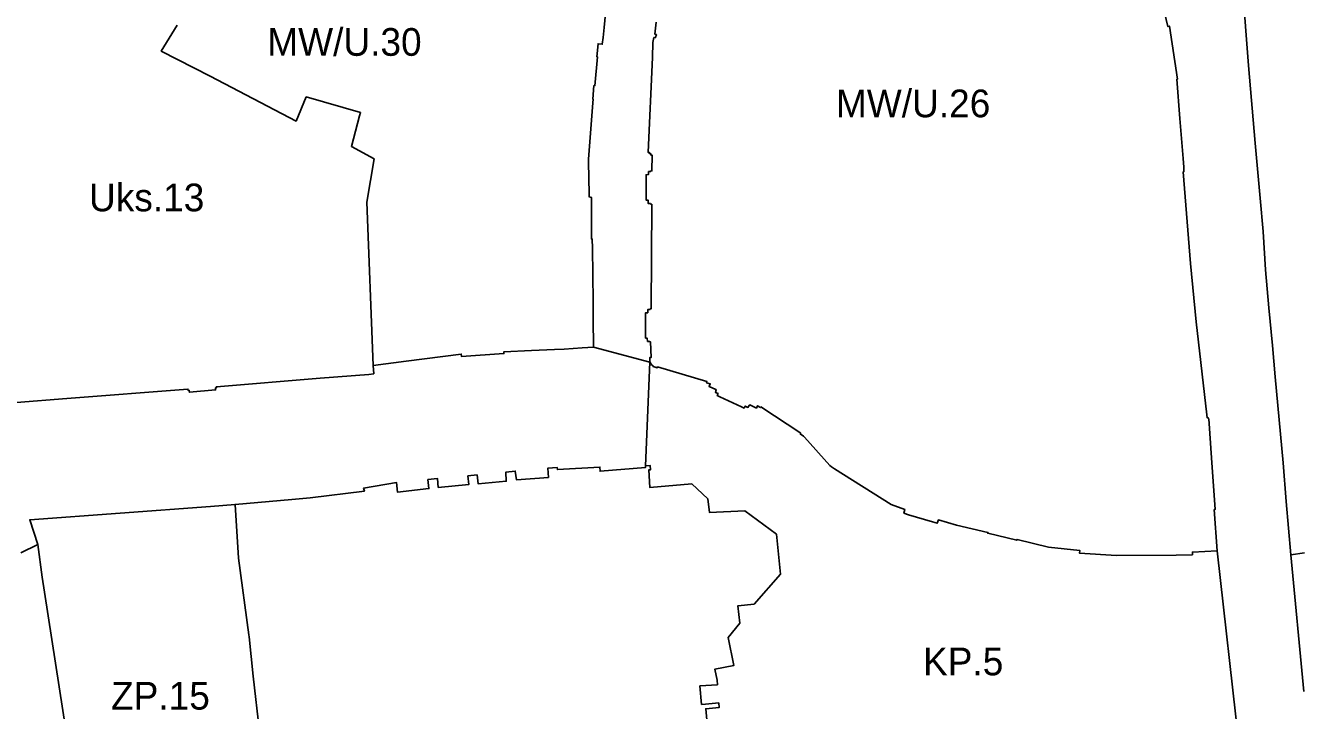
# Model space of a CAD drawing. Extents: x 7423367 to 7424726, y 5546744 to 5548391.
# Drawn here: x 7423725.3 to 7423955.4, y 5547521.4 to 5547645 of the extents above; entities that cross this region are included whole.
import ezdxf

# ---------------------------------------------------------------- set-up
doc = ezdxf.new("R2010")
doc.units = 0
doc.layers.add('linie_rozgraniczajace', color=7, linetype='Continuous')
doc.layers.add('oznaczenia_przeznaczen', color=7, linetype='Continuous')

msp = doc.modelspace()

# ---------------------------------------------------------------- linework, layer by layer
at = {"layer": 'linie_rozgraniczajace'}
for points in [[(7423956.13, 5547549.82), (7423953.67, 5547549.49), (7423952.85, 5547559.12), (7423952.31, 5547566.09), (7423950.87, 5547581.59), (7423950.35, 5547587.25), (7423949.72, 5547594), (7423949.1, 5547600.91), (7423948.68, 5547607.79), (7423948.13, 5547613.84), (7423947.24, 5547623.76), (7423946.05, 5547637.74), (7423944.94, 5547651.91), (7423948.5, 5547670.54), (7423948.98, 5547673.5), (7423949.6, 5547676.37), (7423953.17, 5547690.5), (7423957.42, 5547701.56)], [(7423830.38, 5547651.64), (7423829.69, 5547644.61), (7423829.51, 5547642.82), (7423829.36, 5547641.56), (7423828.61, 5547641.67), (7423828.4, 5547639.3), (7423828.52, 5547639.3), (7423828.06, 5547634.08), (7423827.87, 5547634.11), (7423827.68, 5547631.68), (7423827.73, 5547631.65), (7423827.69, 5547631), (7423826.91, 5547620.83), (7423826.92, 5547620.36), (7423827, 5547614.54), (7423827.01, 5547614.08), (7423827.43, 5547613.95), (7423827.44, 5547613.1), (7423827.43, 5547610.79), (7423827.43, 5547609.35), (7423827.42, 5547606.78), (7423827.42, 5547606.45), (7423827.56, 5547606.44), (7423827.6, 5547604.79), (7423827.71, 5547595.15), (7423827.75, 5547592.07), (7423827.77, 5547586.91), (7423825.74, 5547586.79), (7423822.5, 5547586.59), (7423820.74, 5547586.5), (7423816.61, 5547586.31), (7423811.59, 5547586.07), (7423811.61, 5547585.79), (7423803.98, 5547585.23), (7423803.93, 5547585.7), (7423793.97, 5547584.39), (7423788.01, 5547583.64), (7423786.9, 5547613.11), (7423788.2, 5547620.9), (7423784.08, 5547623.15), (7423785.57, 5547628.66), (7423785.74, 5547629.29), (7423775.95, 5547632.08), (7423774.12, 5547627.73), (7423758.58, 5547635.83), (7423749.78, 5547640.35), (7423752.65, 5547645.04)], [(7423839.09, 5547645.58), (7423838.86, 5547643.41), (7423839.14, 5547643.35), (7423839.01, 5547642.87), (7423838.98, 5547642.75), (7423838.69, 5547642.79), (7423838.52, 5547641.87), (7423838.47, 5547639.2), (7423837.65, 5547622.08), (7423837.85, 5547622.07), (7423837.84, 5547621.87), (7423838.14, 5547621.86), (7423838.15, 5547621.57), (7423838.36, 5547621.57), (7423838.33, 5547618.74), (7423838.13, 5547618.73), (7423838.14, 5547618.63), (7423837.74, 5547618.61), (7423837.72, 5547618.05), (7423837.29, 5547618.04), (7423837.29, 5547617.49), (7423837.29, 5547614), (7423837.28, 5547613.47), (7423837.69, 5547613.44), (7423837.67, 5547612.84), (7423838.08, 5547612.83), (7423838.09, 5547612.73), (7423838.3, 5547612.72), (7423838.19, 5547593.84), (7423838, 5547593.84), (7423838.01, 5547593.74), (7423837.61, 5547593.73), (7423837.6, 5547593.13), (7423837.17, 5547593.12), (7423837.16, 5547592.56), (7423837.19, 5547589.14), (7423837.19, 5547588.57), (7423837.51, 5547588.55), (7423837.57, 5547587.98), (7423837.94, 5547587.96), (7423837.98, 5547587.92), (7423838.09, 5547587.89), (7423838.2, 5547585.07), (7423837.98, 5547585.08), (7423837.96, 5547584.23), (7423827.77, 5547586.91), (7423827.75, 5547592.07), (7423827.71, 5547595.15), (7423827.6, 5547604.79), (7423827.56, 5547606.44), (7423827.42, 5547606.45), (7423827.42, 5547606.78), (7423827.43, 5547609.35), (7423827.43, 5547610.79), (7423827.44, 5547613.1), (7423827.43, 5547613.95), (7423827.01, 5547614.08), (7423827, 5547614.54), (7423826.92, 5547620.36), (7423826.91, 5547620.83), (7423827.69, 5547631), (7423827.73, 5547631.65), (7423827.68, 5547631.68), (7423827.87, 5547634.11), (7423828.06, 5547634.08), (7423828.52, 5547639.3), (7423828.4, 5547639.3), (7423828.61, 5547641.67), (7423829.36, 5547641.56), (7423829.51, 5547642.82), (7423829.69, 5547644.61), (7423830.38, 5547651.64)], [(7423929.54, 5547652.96), (7423931.48, 5547644.77), (7423931.75, 5547644.86), (7423933.22, 5547635.29), (7423933.08, 5547635.27), (7423933.63, 5547628.21), (7423934.22, 5547620.98), (7423934.34, 5547619.39), (7423934.33, 5547618.55), (7423934.21, 5547618.54), (7423935.59, 5547602.03), (7423936.56, 5547591.53), (7423938.5, 5547574.7), (7423938.55, 5547574.21), (7423938.74, 5547574.23), (7423938.77, 5547574.01), (7423938.87, 5547574.02), (7423939.36, 5547567), (7423940.01, 5547557.65), (7423939.86, 5547557.65), (7423940.37, 5547550.19), (7423935.91, 5547549.97), (7423935.92, 5547549.5), (7423932.97, 5547549.43), (7423922.18, 5547549.37), (7423915.52, 5547549.79), (7423915.56, 5547550.28), (7423909.91, 5547550.86), (7423904.25, 5547552.25), (7423904.2, 5547552.12), (7423898.96, 5547553.38), (7423899, 5547553.51), (7423893.33, 5547554.85), (7423890.05, 5547555.76), (7423889.85, 5547555.17), (7423889.01, 5547555.41), (7423884.67, 5547556.72), (7423883.82, 5547557.01), (7423884, 5547557.68), (7423881.52, 5547558.58), (7423871.3, 5547565), (7423870.76, 5547565.35), (7423870.43, 5547565.57), (7423865.88, 5547570.67), (7423865.69, 5547570.87), (7423865.13, 5547571.28), (7423865.2, 5547571.4), (7423858.02, 5547576.17), (7423857.94, 5547576.05), (7423857.4, 5547576.38), (7423857.21, 5547575.95), (7423855.99, 5547576.52), (7423855.94, 5547576.41), (7423855.87, 5547576.43), (7423855.67, 5547576.07), (7423855.18, 5547576.32), (7423854.99, 5547575.94), (7423854.51, 5547576.16), (7423850.6, 5547577.97), (7423850.13, 5547578.19), (7423850.28, 5547578.55), (7423849.79, 5547578.77), (7423849.95, 5547579.18), (7423849.86, 5547579.22), (7423849.9, 5547579.31), (7423848.67, 5547579.86), (7423848.86, 5547580.31), (7423848.2, 5547580.51), (7423848.26, 5547580.72), (7423839.35, 5547583.38), (7423839.3, 5547583.21), (7423838.56, 5547583.44), (7423838.57, 5547583.56), (7423838.22, 5547583.82), (7423838.05, 5547584.22), (7423837.96, 5547584.23), (7423837.98, 5547585.08), (7423838.2, 5547585.07), (7423838.09, 5547587.89), (7423837.98, 5547587.92), (7423837.94, 5547587.96), (7423837.57, 5547587.98), (7423837.51, 5547588.55), (7423837.19, 5547588.57), (7423837.19, 5547589.14), (7423837.16, 5547592.56), (7423837.17, 5547593.12), (7423837.6, 5547593.13), (7423837.61, 5547593.73), (7423838.01, 5547593.74), (7423838, 5547593.84), (7423838.19, 5547593.84), (7423838.3, 5547612.72), (7423838.09, 5547612.73), (7423838.08, 5547612.83), (7423837.67, 5547612.84), (7423837.69, 5547613.44), (7423837.28, 5547613.47), (7423837.29, 5547614), (7423837.29, 5547617.49), (7423837.29, 5547618.04), (7423837.72, 5547618.05), (7423837.74, 5547618.61), (7423838.14, 5547618.63), (7423838.13, 5547618.73), (7423838.33, 5547618.74), (7423838.36, 5547621.57), (7423838.15, 5547621.57), (7423838.14, 5547621.86), (7423837.84, 5547621.87), (7423837.85, 5547622.07), (7423837.65, 5547622.08), (7423838.47, 5547639.2), (7423838.52, 5547641.87), (7423838.69, 5547642.79), (7423838.98, 5547642.75), (7423839.01, 5547642.87), (7423839.14, 5547643.35), (7423838.86, 5547643.41), (7423839.09, 5547645.58)], [(7423944.31, 5547515.44), (7423940.37, 5547550.19), (7423939.86, 5547557.65), (7423940.01, 5547557.65), (7423939.36, 5547567), (7423938.87, 5547574.02), (7423938.77, 5547574.01), (7423938.74, 5547574.23), (7423938.55, 5547574.21), (7423938.5, 5547574.7), (7423936.56, 5547591.53), (7423935.59, 5547602.03), (7423934.21, 5547618.54), (7423934.33, 5547618.55), (7423934.34, 5547619.39), (7423934.22, 5547620.98), (7423933.63, 5547628.21), (7423933.08, 5547635.27), (7423933.22, 5547635.29), (7423931.75, 5547644.86), (7423931.48, 5547644.77), (7423929.54, 5547652.96)], [(7423944.94, 5547651.91), (7423946.05, 5547637.74), (7423947.24, 5547623.76), (7423948.13, 5547613.84), (7423948.68, 5547607.79), (7423949.1, 5547600.91), (7423949.72, 5547594), (7423950.35, 5547587.25), (7423950.87, 5547581.59), (7423952.31, 5547566.09), (7423952.85, 5547559.12), (7423953.67, 5547549.49), (7423956.05, 5547524.84)], [(7423752.65, 5547645.04), (7423749.78, 5547640.35), (7423758.58, 5547635.83), (7423774.12, 5547627.73), (7423775.95, 5547632.08), (7423785.74, 5547629.29), (7423785.57, 5547628.66), (7423784.08, 5547623.15), (7423788.2, 5547620.9), (7423786.9, 5547613.11), (7423788.01, 5547583.64), (7423788.13, 5547582.13), (7423787.22, 5547582), (7423778.43, 5547581.32), (7423759.72, 5547579.79), (7423759.74, 5547579.6), (7423759.54, 5547579.57), (7423759.58, 5547579.21), (7423754.85, 5547578.8), (7423754.81, 5547579.14), (7423754.61, 5547579.14), (7423754.58, 5547579.37), (7423732.75, 5547577.68), (7423723.64, 5547576.96)], [(7423723.64, 5547576.96), (7423732.75, 5547577.68), (7423754.58, 5547579.37), (7423754.61, 5547579.14), (7423754.81, 5547579.14), (7423754.85, 5547578.8), (7423759.58, 5547579.21), (7423759.54, 5547579.57), (7423759.74, 5547579.6), (7423759.72, 5547579.79), (7423778.43, 5547581.32), (7423787.22, 5547582), (7423788.13, 5547582.13), (7423788.01, 5547583.64), (7423793.97, 5547584.39), (7423803.93, 5547585.7), (7423803.98, 5547585.23), (7423811.61, 5547585.79), (7423811.59, 5547586.07), (7423816.61, 5547586.31), (7423820.74, 5547586.5), (7423822.5, 5547586.59), (7423825.74, 5547586.79), (7423827.77, 5547586.91), (7423837.96, 5547584.23), (7423837.2, 5547565.55), (7423837.2, 5547565.24), (7423828.99, 5547564.56), (7423828.95, 5547565.29), (7423821.28, 5547564.85), (7423821.22, 5547565.23), (7423819.56, 5547565.11), (7423819.65, 5547563.44), (7423813.87, 5547563.01), (7423813.66, 5547564.59), (7423811.97, 5547564.41), (7423812.04, 5547562.75), (7423806.97, 5547562.3), (7423806.79, 5547563.88), (7423805.11, 5547563.7), (7423805.26, 5547562.15), (7423799.77, 5547561.63), (7423799.61, 5547563.26), (7423797.9, 5547563.06), (7423798.08, 5547561.42), (7423792.41, 5547560.79), (7423792.25, 5547562.52), (7423786.28, 5547561.51), (7423786.44, 5547560.93), (7423776.67, 5547559.76), (7423773.36, 5547559.43), (7423763.08, 5547558.56), (7423758.63, 5547558.18), (7423726.04, 5547555.81), (7423727.47, 5547551.35), (7423724.4, 5547549.81)], [(7423848.81, 5547513.78), (7423848.07, 5547521.71), (7423850.46, 5547521.91), (7423850.4, 5547522.77), (7423847.99, 5547522.56), (7423847.31, 5547522.49), (7423847.01, 5547525.84), (7423850.15, 5547526.04), (7423850.09, 5547526.88), (7423849.67, 5547528.85), (7423853.15, 5547529.53), (7423852.11, 5547534.59), (7423854.18, 5547537.17), (7423853.87, 5547540.3), (7423856.78, 5547540.59), (7423861.54, 5547545.97), (7423860.82, 5547553.18), (7423855.11, 5547557.43), (7423848.72, 5547557.13), (7423848.44, 5547559.56), (7423845.52, 5547562.28), (7423837.99, 5547561.61), (7423837.77, 5547564.78), (7423838.07, 5547564.79), (7423838, 5547565.61), (7423837.2, 5547565.55), (7423837.96, 5547584.23), (7423838.05, 5547584.22), (7423838.22, 5547583.82), (7423838.57, 5547583.56), (7423838.56, 5547583.44), (7423839.3, 5547583.21), (7423839.35, 5547583.38), (7423848.26, 5547580.72), (7423848.2, 5547580.51), (7423848.86, 5547580.31), (7423848.67, 5547579.86), (7423849.9, 5547579.31), (7423849.86, 5547579.22), (7423849.95, 5547579.18), (7423849.79, 5547578.77), (7423850.28, 5547578.55), (7423850.13, 5547578.19), (7423850.6, 5547577.97), (7423854.51, 5547576.16), (7423854.99, 5547575.94), (7423855.18, 5547576.32), (7423855.67, 5547576.07), (7423855.87, 5547576.43), (7423855.94, 5547576.41), (7423855.99, 5547576.52), (7423857.21, 5547575.95), (7423857.4, 5547576.38), (7423857.94, 5547576.05), (7423858.02, 5547576.17), (7423865.2, 5547571.4), (7423865.13, 5547571.28), (7423865.69, 5547570.87), (7423865.88, 5547570.67), (7423870.43, 5547565.57), (7423870.76, 5547565.35), (7423871.3, 5547565), (7423881.52, 5547558.58), (7423884, 5547557.68), (7423883.82, 5547557.01), (7423884.67, 5547556.72), (7423889.01, 5547555.41), (7423889.85, 5547555.17), (7423890.05, 5547555.76), (7423893.33, 5547554.85), (7423899, 5547553.51), (7423898.96, 5547553.38), (7423904.2, 5547552.12), (7423904.25, 5547552.25), (7423909.91, 5547550.86), (7423915.56, 5547550.28), (7423915.52, 5547549.79), (7423922.18, 5547549.37), (7423932.97, 5547549.43), (7423935.92, 5547549.5), (7423935.91, 5547549.97), (7423940.37, 5547550.19), (7423944.31, 5547515.44)], [(7423767.5, 5547517.6), (7423766.34, 5547527.57), (7423765.64, 5547534.69), (7423765.6, 5547535.06), (7423763.72, 5547548.88), (7423763.08, 5547558.56), (7423773.36, 5547559.43), (7423776.67, 5547559.76), (7423786.44, 5547560.93), (7423786.28, 5547561.51), (7423792.25, 5547562.52), (7423792.41, 5547560.79), (7423798.08, 5547561.42), (7423797.9, 5547563.06), (7423799.61, 5547563.26), (7423799.77, 5547561.63), (7423805.26, 5547562.15), (7423805.11, 5547563.7), (7423806.79, 5547563.88), (7423806.97, 5547562.3), (7423812.04, 5547562.75), (7423811.97, 5547564.41), (7423813.66, 5547564.59), (7423813.87, 5547563.01), (7423819.65, 5547563.44), (7423819.56, 5547565.11), (7423821.22, 5547565.23), (7423821.28, 5547564.85), (7423828.95, 5547565.29), (7423828.99, 5547564.56), (7423837.2, 5547565.24), (7423837.2, 5547565.55), (7423838, 5547565.61), (7423838.07, 5547564.79), (7423837.77, 5547564.78), (7423837.99, 5547561.61), (7423845.52, 5547562.28), (7423848.44, 5547559.56), (7423848.72, 5547557.13), (7423855.11, 5547557.43), (7423860.82, 5547553.18), (7423861.54, 5547545.97), (7423856.78, 5547540.59), (7423853.87, 5547540.3), (7423854.18, 5547537.17), (7423852.11, 5547534.59), (7423853.15, 5547529.53), (7423849.67, 5547528.85), (7423850.09, 5547526.88), (7423850.15, 5547526.04), (7423847.01, 5547525.84), (7423847.31, 5547522.49), (7423847.99, 5547522.56), (7423850.4, 5547522.77), (7423850.46, 5547521.91), (7423848.07, 5547521.71), (7423848.81, 5547513.78)], [(7423724.4, 5547549.81), (7423727.47, 5547551.35), (7423728.28, 5547545.46), (7423728.69, 5547542.72), (7423733.35, 5547512.87), (7423732.81, 5547512.77), (7423735.11, 5547496.61), (7423735.65, 5547492.87), (7423735.89, 5547491.17), (7423736.28, 5547488.56), (7423736.48, 5547487.27), (7423741.93, 5547462.77), (7423741.4, 5547462.68), (7423742.95, 5547453.93), (7423753.89, 5547405.68), (7423754.09, 5547404.21), (7423748.29, 5547403.79), (7423735.54, 5547402.61), (7423717.1, 5547400.73)], [(7423956.05, 5547524.84), (7423953.67, 5547549.49), (7423956.13, 5547549.82)]]:
    msp.add_lwpolyline(points, dxfattribs=at)
msp.add_lwpolyline([(7423726.04, 5547555.81), (7423758.63, 5547558.18), (7423763.08, 5547558.56), (7423763.72, 5547548.88), (7423765.6, 5547535.06), (7423765.64, 5547534.69), (7423766.34, 5547527.57), (7423767.5, 5547517.6), (7423771.76, 5547509.04), (7423767.07, 5547506.04), (7423770.15, 5547493.68), (7423759.15, 5547491.46), (7423745.76, 5547488.88), (7423745.02, 5547488.75), (7423736.48, 5547487.27), (7423736.28, 5547488.56), (7423735.89, 5547491.17), (7423735.65, 5547492.87), (7423735.11, 5547496.61), (7423732.81, 5547512.77), (7423733.35, 5547512.87), (7423728.69, 5547542.72), (7423728.28, 5547545.46), (7423727.47, 5547551.35)], close=True, dxfattribs=at)

# ---------------------------------------------------------------- texts
at = {"layer": 'oznaczenia_przeznaczen'}
for s, p in [('MW/U.30', (7423768.91, 5547639.49)), ('MW/U.26', (7423871.56, 5547628.4)), ('Uks.13', (7423736.73, 5547611.44)), ('KP.5', (7423887.28, 5547527.74)), ('ZP.15', (7423740.7, 5547521.56))]:
    msp.add_text(s, height=5, dxfattribs=at).set_placement(p)

doc.saveas('drawing.dxf')
